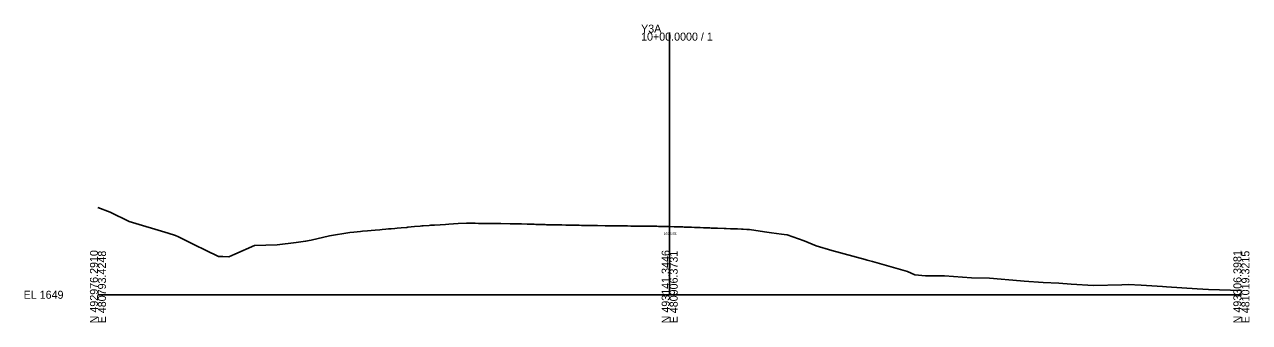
# Model space of a CAD drawing. Extents: x -26 to 403, y -10 to 3108.
# Drawn here: x -25.7 to 402.8, y -9.7 to 94.5 of the extents above; entities that cross this region are included whole.
import ezdxf

# ---------------------------------------------------------------- set-up
doc = ezdxf.new("R2010")
doc.units = 0
for name, color, linetype in [('Exist Cross Section Cell', 7, 'Continuous'), ('Exist XS Center Line Elevation Label', 7, 'Continuous'), ('Exist XS Ground Line', 7, 'Continuous')]:
    doc.layers.add(name, color=color, linetype=linetype)

msp = doc.modelspace()

# ---------------------------------------------------------------- linework, layer by layer
at = {"layer": 'Exist Cross Section Cell'}
for p, q in [((200, 0), (200, 91.64)), ((0, 0), (200, 0)), ((200, 0), (400, 0))]:
    msp.add_line(p, q, dxfattribs=at)
at = {"layer": 'Exist XS Ground Line'}
msp.add_lwpolyline([(0, 30.55), (4.32, 28.89), (10.88, 25.62), (24.52, 21.56), (27.12, 20.68), (28.18, 20.21), (32.8, 17.96), (38.5, 15.18), (41.23, 13.87), (42.14, 13.4), (43.68, 13.36), (45.75, 13.26), (47.94, 14.21), (54.78, 17.2), (62.64, 17.48), (69.32, 18.3), (72.62, 18.71), (74.61, 19.09), (81.02, 20.65), (88.06, 21.78), (89.52, 21.91), (90.64, 22.02), (91.83, 22.13), (92.57, 22.2), (94.27, 22.35), (95.6, 22.46), (96.92, 22.58), (98.58, 22.74), (99.4, 22.81), (100.7, 22.93), (101.63, 23.01), (102.57, 23.1), (103.86, 23.21), (104.62, 23.28), (106.12, 23.41), (108, 23.57), (108.39, 23.61), (110.74, 23.82), (112.71, 24), (113.31, 24.05), (113.72, 24.09), (115.88, 24.25), (116.39, 24.29), (117.16, 24.34), (117.75, 24.37), (119.77, 24.48), (121.57, 24.59), (122.79, 24.66), (125.98, 24.86), (128.94, 24.98), (130.46, 25), (131.97, 24.98), (133.15, 24.97), (134.85, 24.94), (138.03, 24.89), (138.49, 24.89), (139.26, 24.88), (140.27, 24.88), (140.98, 24.87), (144.15, 24.84), (145.67, 24.81), (147.14, 24.77), (147.6, 24.76), (148.2, 24.75), (150.13, 24.7), (151.12, 24.68), (152.59, 24.63), (153.15, 24.61), (154.43, 24.57), (156.18, 24.52), (156.5, 24.51), (156.96, 24.5), (159.23, 24.45), (160.12, 24.43), (161.41, 24.41), (162.25, 24.39), (163.72, 24.36), (165.51, 24.32), (165.85, 24.32), (168.29, 24.28), (169.1, 24.26), (170.29, 24.25), (170.91, 24.24), (171.34, 24.24), (173.59, 24.2), (174.35, 24.19), (174.71, 24.19), (177.4, 24.15), (179.12, 24.13), (180.41, 24.12), (181.69, 24.1), (183.55, 24.08), (185.27, 24.05), (186.47, 24.03), (187.09, 24.03), (187.98, 24.02), (188.88, 24.01), (189.5, 24.01), (190.68, 24), (192.52, 23.98), (194.27, 23.96), (195.55, 23.94), (196.07, 23.92), (196.83, 23.91), (197.87, 23.89), (198.57, 23.88), (199.67, 23.84), (200, 23.83), (201.59, 23.79), (203.27, 23.74), (204.61, 23.69), (205.06, 23.67), (205.72, 23.65), (206.86, 23.61), (207.63, 23.58), (208.66, 23.54), (210.15, 23.49), (210.67, 23.47), (211.82, 23.43), (213.7, 23.36), (214.05, 23.35), (214.57, 23.33), (215.86, 23.28), (216.73, 23.25), (219.01, 23.17), (219.45, 23.15), (219.75, 23.14), (221.31, 23.08), (222.66, 23.03), (223.74, 23), (225.13, 22.95), (225.67, 22.93), (227.05, 22.85), (227.88, 22.81), (233.22, 22), (235.6, 21.68), (239.17, 21.2), (240.03, 21.09), (241.16, 20.91), (247.04, 18.82), (251.27, 17.15), (256.74, 15.43), (268.41, 12.33), (269.1, 12.14), (270.97, 11.64), (283.2, 8.17), (285.73, 6.99), (289.45, 6.66), (296.15, 6.64), (305.63, 5.92), (311.87, 5.82), (322.78, 4.87), (323.98, 4.72), (330.69, 4.24), (336.1, 4), (340.49, 3.7), (348.22, 3.22), (358.2, 3.51), (360.34, 3.59), (364.99, 3.3), (372.46, 2.85), (373.86, 2.8), (384.58, 2.05), (388.48, 1.79), (400, 1.49)], dxfattribs=at)

# ---------------------------------------------------------------- texts
at = {"layer": 'Exist Cross Section Cell'}
for s, p in [('Y3A', (190, 91.64)), ('10+00.0000 / 1', (190, 88.84)), ('EL 1649', (-26, -1.4))]:
    msp.add_text(s, height=2.8, dxfattribs=at).set_placement(p)
for s, p in [('N 492976.2910', (0, -10)), ('E 480793.4248', (2.8, -10)), ('N 493141.3446', (200, -10)), ('E 480906.3731', (202.8, -10)), ('N 493306.3981', (400, -10)), ('E 481019.3215', (402.8, -10))]:
    msp.add_text(s, height=2.8, rotation=90, dxfattribs=at).set_placement(p)
at = {"layer": 'Exist XS Center Line Elevation Label'}
msp.add_text('1672.83', height=0.9, dxfattribs=at).set_placement((197.87, 20.93))

doc.saveas('drawing.dxf')
